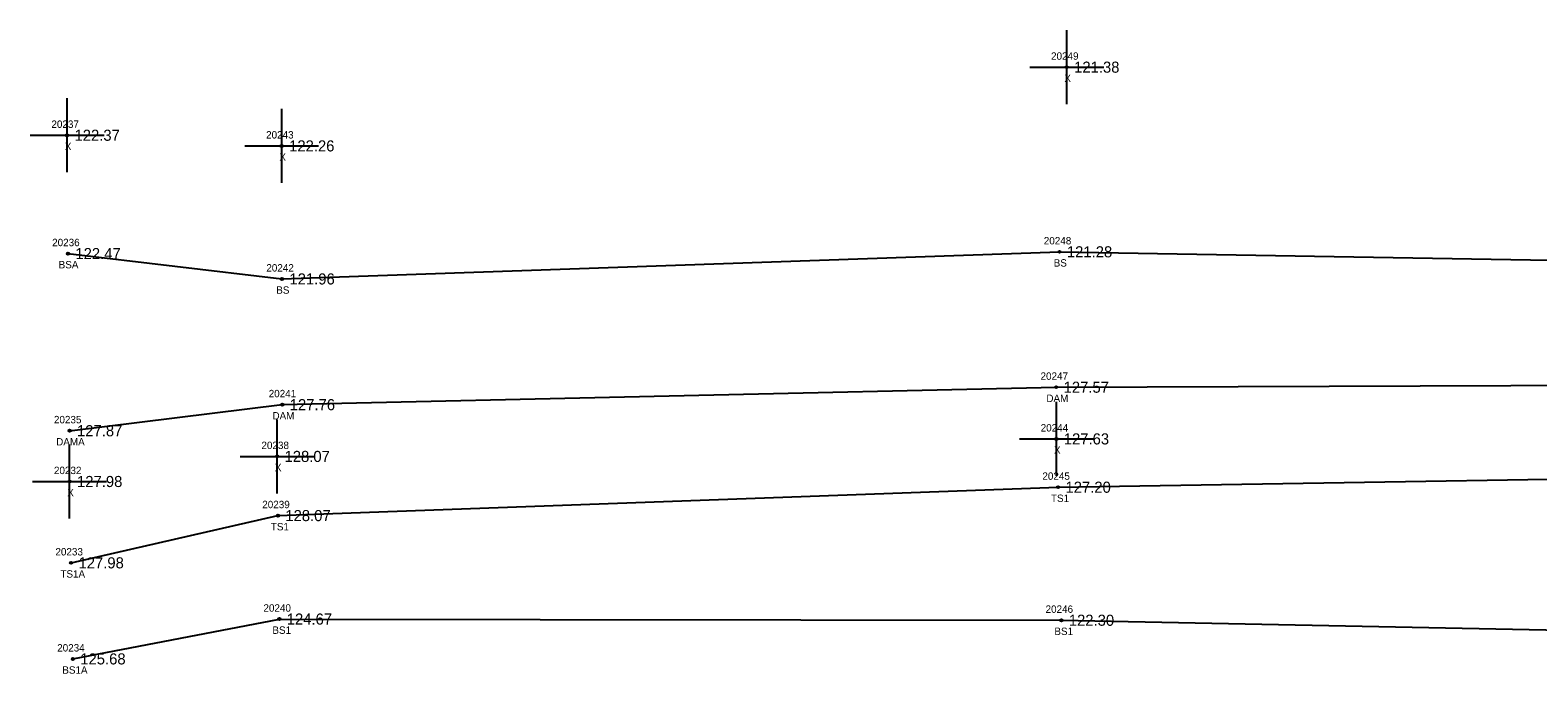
# Model space of a CAD drawing. Extents: x 2375812 to 2377225, y 1024470 to 1025135.
# Drawn here: x 2375842.4 to 2376046.3, y 1025035.3 to 1025122.4 of the extents above; entities that cross this region are included whole.
import ezdxf

# ---------------------------------------------------------------- set-up
doc = ezdxf.new("R2010")
doc.units = 0
for name, color, linetype in [('RD_DTM_BkLn2', 7, 'Continuous'), ('RD_DTM_BkLn_txCode', 7, 'Continuous'), ('RD_EX_Dam', 7, 'Continuous'), ('RD_EX_Dam_txCode', 7, 'Continuous'), ('RD_EX_Misc', 7, 'Continuous'), ('RD_EX_Misc_txCode', 7, 'Continuous'), ('RD_EX_TX_Dam_ELEV', 7, 'Continuous'), ('RD_EX_TX_Misc_ELEV', 7, 'Continuous'), ('RD_SMD_Locator', 7, 'Continuous')]:
    doc.layers.add(name, color=color, linetype=linetype)

msp = doc.modelspace()

# ---------------------------------------------------------------- linework, layer by layer
at = {"layer": 'RD_DTM_BkLn2'}
for points in [[(2375847.51, 1025092.15), (2375876.46, 1025088.72), (2375981.63, 1025092.39), (2376090.5, 1025090.54), (2376205.11, 1025096.35), (2376313.64, 1025091.79), (2376415.11, 1025100.3), (2376448.24, 1025100.64), (2376465.02, 1025111.39), (2376486.46, 1025115.19), (2376497.97, 1025114.18)], [(2375847.93, 1025050.33), (2375875.91, 1025056.72), (2375981.44, 1025060.56), (2376091.98, 1025062.38), (2376205.71, 1025062.75), (2376313.72, 1025064.62), (2376418.13, 1025064.73), (2376493.03, 1025062.01)], [(2375848.17, 1025037.34), (2375876.1, 1025042.73), (2375981.89, 1025042.57), (2376092.59, 1025040.39), (2376206.51, 1025041.77), (2376314.64, 1025046.65), (2376420.66, 1025046.91), (2376483.6, 1025044.87), (2376501.85, 1025058.56), (2376497.33, 1025064.77)]]:
    msp.add_lwpolyline(points, dxfattribs=at)
at = {"layer": 'RD_EX_Dam'}
msp.add_lwpolyline([(2375847.73, 1025068.2), (2375876.5, 1025071.72), (2375981.19, 1025074.08), (2376091.91, 1025074.48), (2376205.24, 1025076.35), (2376314.21, 1025075.97), (2376418.29, 1025077.81), (2376454.32, 1025078.43), (2376493.3, 1025082.7)], dxfattribs=at)
at = {"layer": 'RD_EX_Misc'}
for p, q in [((2375982.61, 1025112.36), (2375982.61, 1025122.36)), ((2375977.61, 1025117.36), (2375987.61, 1025117.36)), ((2375847.39, 1025103.15), (2375847.39, 1025113.15)), ((2375876.42, 1025101.71), (2375876.42, 1025111.71)), ((2375842.39, 1025108.15), (2375852.39, 1025108.15)), ((2375871.42, 1025106.71), (2375881.42, 1025106.71)), ((2375981.21, 1025062.09), (2375981.21, 1025072.09)), ((2375875.8, 1025059.72), (2375875.8, 1025069.72)), ((2375976.21, 1025067.09), (2375986.21, 1025067.09)), ((2375847.73, 1025056.33), (2375847.73, 1025066.33)), ((2375870.8, 1025064.72), (2375880.8, 1025064.72)), ((2375842.73, 1025061.33), (2375852.73, 1025061.33))]:
    msp.add_line(p, q, dxfattribs=at)
at = {"layer": 'RD_SMD_Locator'}
for centre in [(2375982.61, 1025117.36), (2375847.39, 1025108.15), (2375876.42, 1025106.71), (2375847.51, 1025092.15), (2375981.63, 1025092.39), (2375876.46, 1025088.72), (2375981.19, 1025074.08), (2375876.5, 1025071.72), (2375847.73, 1025068.2), (2375981.21, 1025067.09), (2375875.8, 1025064.72), (2375847.73, 1025061.33), (2375981.44, 1025060.56), (2375875.91, 1025056.72), (2375847.93, 1025050.33), (2375876.1, 1025042.73), (2375981.89, 1025042.57), (2375848.17, 1025037.34)]:
    msp.add_circle(centre, 0.15, dxfattribs=at)

# ---------------------------------------------------------------- texts
at = {"layer": 'RD_DTM_BkLn_txCode'}
for s, p in [('20236', (2375845.37, 1025093.15)), ('20248', (2375979.51, 1025093.39)), ('BS', (2375980.85, 1025090.39)), ('BSA', (2375846.25, 1025090.15)), ('20242', (2375874.34, 1025089.72)), ('BS', (2375875.68, 1025086.72)), ('20245', (2375979.32, 1025061.56)), ('20239', (2375873.79, 1025057.72)), ('TS1', (2375980.48, 1025058.56)), ('TS1', (2375874.95, 1025054.72)), ('20233', (2375845.81, 1025051.33)), ('TS1A', (2375846.48, 1025048.33)), ('20240', (2375873.95, 1025043.73)), ('20246', (2375979.75, 1025043.57)), ('BS1', (2375875.16, 1025040.73)), ('BS1', (2375980.94, 1025040.57)), ('20234', (2375846.05, 1025038.34)), ('BS1A', (2375846.74, 1025035.34))]:
    msp.add_text(s, height=1, dxfattribs=at).set_placement(p)
at = {"layer": 'RD_EX_Dam_txCode'}
for s, p in [('20247', (2375979.07, 1025075.08)), ('20241', (2375874.66, 1025072.72)), ('DAM', (2375979.86, 1025072.08)), ('20235', (2375845.61, 1025069.2)), ('DAM', (2375875.17, 1025069.72)), ('DAMA', (2375845.91, 1025066.2))]:
    msp.add_text(s, height=1, dxfattribs=at).set_placement(p)
at = {"layer": 'RD_EX_Misc_txCode'}
for s, p in [('20249', (2375980.49, 1025118.36)), ('X', (2375982.29, 1025115.36)), ('20237', (2375845.27, 1025109.15)), ('20243', (2375874.31, 1025107.71)), ('X', (2375847.08, 1025106.15)), ('X', (2375876.11, 1025104.71)), ('20244', (2375979.09, 1025068.09)), ('20238', (2375873.68, 1025065.72)), ('X', (2375980.89, 1025065.09)), ('20232', (2375845.61, 1025062.33)), ('X', (2375875.49, 1025062.72)), ('X', (2375847.41, 1025059.33))]:
    msp.add_text(s, height=1, dxfattribs=at).set_placement(p)
at = {"layer": 'RD_EX_TX_Dam_ELEV'}
for s, p in [('127.57', (2375982.19, 1025073.33)), ('127.76', (2375877.5, 1025070.97)), ('127.87', (2375848.73, 1025067.45))]:
    msp.add_text(s, height=1.5, dxfattribs=at).set_placement(p)
at = {"layer": 'RD_EX_TX_Misc_ELEV'}
for s, p in [('121.38', (2375983.61, 1025116.61)), ('122.37', (2375848.39, 1025107.4)), ('122.26', (2375877.42, 1025105.96)), ('122.47', (2375848.51, 1025091.4)), ('121.28', (2375982.63, 1025091.64)), ('121.96', (2375877.46, 1025087.97)), ('127.63', (2375982.21, 1025066.34)), ('128.07', (2375876.8, 1025063.97)), ('127.98', (2375848.73, 1025060.58)), ('127.20', (2375982.44, 1025059.81)), ('128.07', (2375876.91, 1025055.97)), ('127.98', (2375848.93, 1025049.58)), ('124.67', (2375877.1, 1025041.98)), ('122.30', (2375982.89, 1025041.82)), ('125.68', (2375849.17, 1025036.59))]:
    msp.add_text(s, height=1.5, dxfattribs=at).set_placement(p)

doc.saveas('drawing.dxf')
